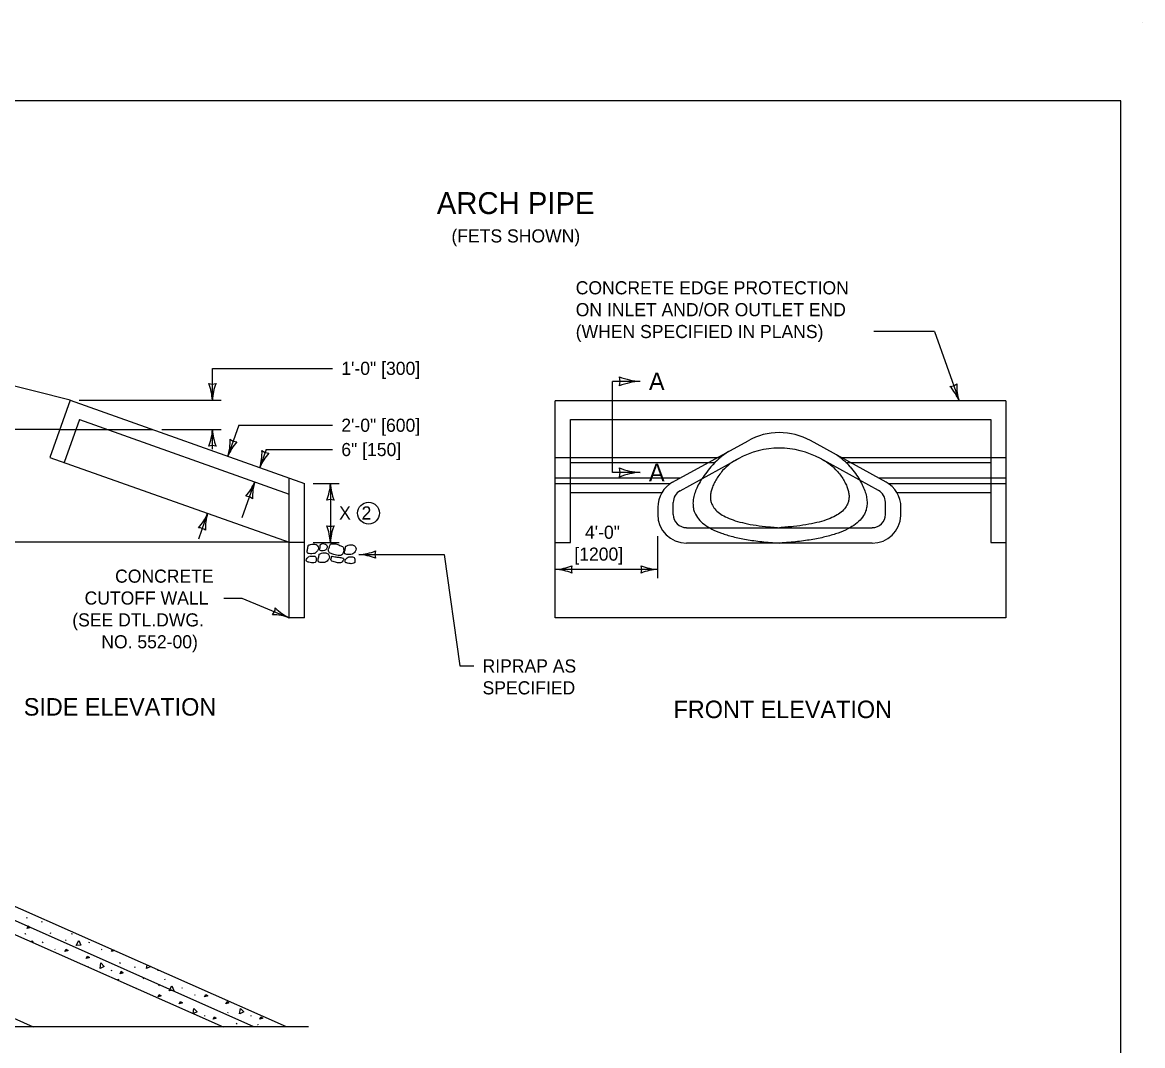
# Model space of a CAD drawing. Extents: x 49991.4 to 50021, y 49987.6 to 50011.4.
# Drawn here: x 50015.92 to 50021.04, y 50003.85 to 50008.52 of the extents above; entities that cross this region are included whole.
import ezdxf

# ---------------------------------------------------------------- set-up
doc = ezdxf.new("R2010")
doc.units = 0
for name, color, linetype in [('Level 1', 7, 'Continuous'), ('Level 2', 7, 'Continuous'), ('Level 3', 7, 'Continuous'), ('Level 4', 7, 'Continuous'), ('Level 6', 7, 'Continuous')]:
    doc.layers.add(name, color=color, linetype=linetype)

msp = doc.modelspace()

# ---------------------------------------------------------------- linework, layer by layer
at = {"layer": 'Level 1'}
for p, q in [((50021.0378, 50008.5236), (50021.0378, 50008.5236)), ((50016.1364, 50006.7969), (50015.5405, 50006.9461)), ((50016.1364, 50006.7969), (50016.0435, 50006.5354)), ((50016.1364, 50006.7969), (50017.2067, 50006.4165)), ((50020.413, 50006.7939), (50018.3534, 50006.7939)), ((50018.3534, 50005.8027), (50018.3534, 50006.7939)), ((50020.413, 50006.7939), (50020.413, 50005.8027)), ((50016.0887, 50006.6627), (50015.6302, 50006.6627)), ((50018.8896, 50006.4219), (50019.2342, 50006.6118)), ((50019.865, 50006.4228), (50019.5201, 50006.612)), ((50016.0435, 50006.5354), (50017.1373, 50006.1472)), ((50018.9237, 50006.3831), (50019.1893, 50006.5293)), ((50019.8309, 50006.3837), (50019.5648, 50006.5297)), ((50017.1373, 50005.8027), (50017.1373, 50006.4412)), ((50018.3534, 50006.4412), (50018.9246, 50006.4412)), ((50019.8314, 50006.4412), (50020.413, 50006.4412)), ((50017.2067, 50005.8027), (50017.2067, 50006.4165)), ((50018.3534, 50006.4165), (50018.8806, 50006.4165)), ((50019.8753, 50006.4165), (50020.413, 50006.4165)), ((50018.8924, 50006.2748), (50018.8924, 50006.3299)), ((50019.8624, 50006.2748), (50019.8624, 50006.3306)), ((50018.8215, 50006.3067), (50018.8215, 50006.2748)), ((50019.9331, 50006.2693), (50019.9332, 50006.3075)), ((50018.953, 50006.2141), (50019.8017, 50006.2141)), ((50017.1373, 50006.1472), (50015.6335, 50006.1472)), ((50017.3942, 50006.1287), (50017.3955, 50006.1295)), ((50019.8017, 50006.1433), (50018.953, 50006.1433)), ((50017.273, 50006.0923), (50017.2743, 50006.0931)), ((50017.2067, 50005.8027), (50017.1373, 50005.8027)), ((50020.413, 50005.8027), (50018.3534, 50005.8027)), ((50017.1247, 50003.9332), (50014.8623, 50004.9337)), ((50016.9755, 50003.9332), (50014.8922, 50004.8567)), ((50014.922, 50004.7792), (50016.8348, 50003.9332)), ((50015.938, 50004.4293), (50015.9398, 50004.4333)), ((50016.0055, 50004.4111), (50016.0073, 50004.4151)), ((50015.9287, 50004.3596), (50015.9304, 50004.3569)), ((50015.9304, 50004.3586), (50015.9322, 50004.3559)), ((50016.0459, 50004.3596), (50016.0477, 50004.3636)), ((50016.1413, 50004.3596), (50016.1431, 50004.3569)), ((50016.1431, 50004.3586), (50016.1449, 50004.3559)), ((50016.0099, 50004.3165), (50016.0117, 50004.3205)), ((50016.0654, 50004.2881), (50016.0672, 50004.2854)), ((50016.1151, 50004.3267), (50016.1169, 50004.3307)), ((50016.2226, 50004.3165), (50016.2244, 50004.3205)), ((50016.2781, 50004.2881), (50016.2799, 50004.2854)), ((50016.219, 50004.2056), (50016.2199, 50004.2077)), ((50016.3237, 50004.1926), (50016.3242, 50004.1886)), ((50016.3634, 50004.2219), (50016.3651, 50004.2259)), ((50016.4309, 50004.2037), (50016.4326, 50004.2077)), ((50016.5364, 50004.1926), (50016.5369, 50004.1886)), ((50016.354, 50004.1522), (50016.3558, 50004.1495)), ((50016.3558, 50004.1512), (50016.3576, 50004.1485)), ((50016.4713, 50004.1522), (50016.473, 50004.1562)), ((50016.5667, 50004.1522), (50016.5685, 50004.1495)), ((50016.5685, 50004.1512), (50016.5703, 50004.1485)), ((50016.4356, 50004.1098), (50016.4371, 50004.1131)), ((50016.5405, 50004.1193), (50016.5423, 50004.1233)), ((50016.648, 50004.1091), (50016.6498, 50004.1131)), ((50016.7035, 50004.0807), (50016.7053, 50004.078)), ((50016.7491, 50003.9851), (50016.7495, 50003.9811)), ((50016.7887, 50004.0145), (50016.7905, 50004.0185)), ((50016.8562, 50003.9963), (50016.858, 50004.0003)), ((50016.9618, 50003.9851), (50016.9622, 50003.9811)), ((50016.8966, 50003.9448), (50016.8984, 50003.9488)), ((50016.9921, 50003.9448), (50016.9939, 50003.9421)), ((50016.9939, 50003.9438), (50016.9957, 50003.9411)), ((50017.1247, 50003.9332), (50017.1247, 50003.9332))]:
    msp.add_line(p, q, dxfattribs=at)
msp.add_lwpolyline([(50020.9378, 50008.1646), (50009.7374, 50008.1646), (50009.7374, 49999.8856), (50020.9378, 49999.8856)], close=True, dxfattribs=at)
for points in [[(50015.9389, 50004.3827), (50015.9442, 50004.3938), (50015.9531, 50004.3871), (50015.9389, 50004.3827)], [(50015.9586, 50004.3207), (50015.962, 50004.3271), (50015.9664, 50004.3173)], [(50016.112, 50004.2765), (50016.1174, 50004.2876), (50016.1262, 50004.281), (50016.112, 50004.2765)], [(50016.1627, 50004.3045), (50016.1747, 50004.3271), (50016.184, 50004.3063), (50016.1631, 50004.3045)], [(50016.3247, 50004.2765), (50016.3289, 50004.2851)], [(50016.2094, 50004.2448), (50016.2147, 50004.2559), (50016.2236, 50004.2492), (50016.2094, 50004.2448)], [(50016.3385, 50004.2809), (50016.3247, 50004.2765)], [(50016.2722, 50004.1991), (50016.2757, 50004.2245), (50016.2916, 50004.2081), (50016.2726, 50004.1993)], [(50016.3643, 50004.1753), (50016.3696, 50004.1864), (50016.3785, 50004.1797), (50016.3643, 50004.1753)], [(50016.4849, 50004.1991), (50016.4871, 50004.2152)], [(50016.5037, 50004.2078), (50016.4853, 50004.1993)], [(50016.5769, 50004.1753), (50016.577, 50004.1754)], [(50016.5771, 50004.1754), (50016.5769, 50004.1753)], [(50016.5374, 50004.0691), (50016.5427, 50004.0802), (50016.5516, 50004.0736), (50016.5374, 50004.0691)], [(50016.588, 50004.0971), (50016.6, 50004.1197), (50016.6094, 50004.0989), (50016.5885, 50004.0971)], [(50016.7501, 50004.0691), (50016.7554, 50004.0802), (50016.7643, 50004.0736), (50016.7501, 50004.0691)], [(50016.6347, 50004.0374), (50016.6401, 50004.0485), (50016.649, 50004.0418), (50016.6347, 50004.0374)], [(50016.8474, 50004.0374), (50016.8528, 50004.0485), (50016.8616, 50004.0418), (50016.8474, 50004.0374)], [(50016.6979, 50003.9938), (50016.7011, 50004.0171), (50016.717, 50004.0007), (50016.7, 50003.9928)], [(50016.7896, 50003.9679), (50016.795, 50003.979), (50016.8038, 50003.9723), (50016.7896, 50003.9679)], [(50016.9102, 50003.9917), (50016.9138, 50004.0171), (50016.9297, 50004.0007), (50016.9107, 50003.9919)], [(50017.0023, 50003.9679), (50017.0076, 50003.979), (50017.0165, 50003.9723), (50017.0023, 50003.9679)]]:
    msp.add_lwpolyline(points, dxfattribs=at)
for centre, major_axis, start_param, end_param in [((50019.3773, 50006.3519), (0, 0.2967), 5.781332, 6.786673), ((50019.3773, 50006.188), (0, 0.3897), 5.781311, 6.786734), ((50019.3162, 50006.2891), (0, 0.2717), 0.485979, 0.816691), ((50019.4459, 50006.2851), (0, 0.2717), 5.466495, 5.799741), ((50018.953, 50006.3067), (0, 0.1315), 0.503156, 1.570796), ((50018.953, 50006.3299), (0, 0.0606), 0.503453, 1.570796), ((50019.8017, 50006.3306), (0, 0.0606), 4.712389, 5.781265), ((50019.8017, 50006.3075), (0, 0.1315), 4.712389, 5.781202), ((50018.953, 50006.2748), (0, -0.1315), 4.712389, 6.283185), ((50018.953, 50006.2748), (0, -0.0606), 4.712389, 6.283185), ((50019.8017, 50006.2748), (0, -0.0606), 0, 1.570796), ((50019.8017, 50006.2748), (0, -0.1315), 0, 1.528873)]:
    msp.add_ellipse(centre, major_axis=major_axis, ratio=0.999965, start_param=start_param, end_param=end_param, dxfattribs=at)
for points in [[(50019.1181, 50006.4752), (50018.9295, 50006.242), (50019.3774, 50006.2141)], [(50019.6439, 50006.4711), (50019.825, 50006.2419), (50019.3774, 50006.2141)]]:
    msp.add_open_spline(points, degree=2, dxfattribs=at)
for points in [[(50017.2229, 50006.1324), (50017.2349, 50006.1374), (50017.2476, 50006.139), (50017.2609, 50006.1367), (50017.267, 50006.1315), (50017.271, 50006.1205), (50017.2664, 50006.1088), (50017.2534, 50006.0968), (50017.2411, 50006.0953), (50017.2284, 50006.0956), (50017.2204, 50006.0986), (50017.2192, 50006.1083), (50017.2207, 50006.1162), (50017.2225, 50006.1247), (50017.2243, 50006.133)], [(50017.28, 50006.1364), (50017.2857, 50006.1409), (50017.2975, 50006.1401), (50017.3081, 50006.1356), (50017.3105, 50006.1236), (50017.3038, 50006.1121), (50017.2922, 50006.1088), (50017.2763, 50006.1114), (50017.2763, 50006.1191), (50017.2785, 50006.1268), (50017.2782, 50006.1346), (50017.2802, 50006.1369)], [(50017.3158, 50006.1124), (50017.3205, 50006.1263), (50017.3257, 50006.1384), (50017.3332, 50006.1402), (50017.3496, 50006.1397), (50017.3687, 50006.133), (50017.383, 50006.1249), (50017.386, 50006.1088), (50017.3781, 50006.0906), (50017.3666, 50006.0863), (50017.3411, 50006.092), (50017.3243, 50006.0976), (50017.3163, 50006.1069), (50017.3158, 50006.1126)], [(50017.3942, 50006.1287), (50017.4063, 50006.1337), (50017.4189, 50006.1355), (50017.4321, 50006.133), (50017.4384, 50006.1278), (50017.4424, 50006.1168), (50017.4377, 50006.1051), (50017.4247, 50006.0932), (50017.4125, 50006.0915), (50017.3997, 50006.092), (50017.3917, 50006.0948), (50017.3904, 50006.1045), (50017.3921, 50006.1125), (50017.3938, 50006.1211), (50017.3955, 50006.1295)], [(50017.2293, 50006.0832), (50017.2367, 50006.0841), (50017.2452, 50006.0839), (50017.2542, 50006.0833), (50017.2585, 50006.0791), (50017.2595, 50006.0676), (50017.2594, 50006.0584), (50017.2493, 50006.0536), (50017.2271, 50006.056), (50017.2156, 50006.0616), (50017.2164, 50006.0705), (50017.2217, 50006.0774), (50017.2289, 50006.0829)], [(50017.273, 50006.0923), (50017.2851, 50006.0973), (50017.2977, 50006.0991), (50017.3109, 50006.0966), (50017.3172, 50006.0914), (50017.3212, 50006.0804), (50017.3165, 50006.0687), (50017.3035, 50006.0568), (50017.2913, 50006.0551), (50017.2785, 50006.0556), (50017.2705, 50006.0584), (50017.2692, 50006.0681), (50017.2709, 50006.0761), (50017.2726, 50006.0847), (50017.2743, 50006.0931)], [(50017.3335, 50006.0843), (50017.3454, 50006.0811), (50017.3633, 50006.0786), (50017.3821, 50006.0753), (50017.3854, 50006.073), (50017.3821, 50006.0619), (50017.3756, 50006.0546), (50017.3576, 50006.0538), (50017.3381, 50006.0592), (50017.3285, 50006.0642), (50017.3286, 50006.0734), (50017.3318, 50006.0825), (50017.3329, 50006.0843)], [(50017.4063, 50006.0794), (50017.4134, 50006.0806), (50017.422, 50006.0802), (50017.4312, 50006.0796), (50017.4354, 50006.0753), (50017.4364, 50006.064), (50017.4362, 50006.0547), (50017.4261, 50006.0499), (50017.4039, 50006.0522), (50017.3925, 50006.0578), (50017.3934, 50006.0667), (50017.3984, 50006.0736), (50017.4057, 50006.0793)]]:
    msp.add_spline(points, degree=3, dxfattribs=at)
at = {"layer": 'Level 2'}
msp.add_circle((50017.4997, 50006.2807), 0.05, dxfattribs=at)
at = {"layer": 'Level 3'}
for p, q in [((50020.0861, 50007.1106), (50019.8089, 50007.1106)), ((50020.0861, 50007.1106), (50020.1986, 50006.7939)), ((50016.7858, 50006.797), (50016.7858, 50006.9424)), ((50016.7858, 50006.9424), (50017.3351, 50006.9424)), ((50016.1764, 50006.797), (50016.8258, 50006.797)), ((50016.554, 50006.6627), (50016.8258, 50006.6627)), ((50016.7858, 50006.5732), (50016.7858, 50006.6627)), ((50016.907, 50006.6824), (50016.8567, 50006.5409)), ((50016.907, 50006.6824), (50017.3351, 50006.6824)), ((50017.032, 50006.5713), (50017.0027, 50006.489)), ((50017.032, 50006.5713), (50017.3351, 50006.5713)), ((50016.9214, 50006.2603), (50016.9795, 50006.4237)), ((50017.2467, 50006.416), (50017.3651, 50006.416)), ((50017.3251, 50006.416), (50017.3251, 50006.1469)), ((50016.7638, 50006.2797), (50016.7221, 50006.1623)), ((50017.2467, 50006.1469), (50017.3651, 50006.1469)), ((50018.8215, 50005.9833), (50018.8215, 50006.1748)), ((50017.4553, 50006.0911), (50017.8452, 50006.0911)), ((50017.8452, 50006.0911), (50017.9169, 50005.5821)), ((50018.8215, 50006.0233), (50018.3534, 50006.0233)), ((50016.8383, 50005.8926), (50016.9202, 50005.8926)), ((50016.9202, 50005.8926), (50017.1373, 50005.8027)), ((50017.9169, 50005.5821), (50017.9807, 50005.5821))]:
    msp.add_line(p, q, dxfattribs=at)
for centre, radius, start, end in [((50018.7528, 50007.1607), 0.2779, 247.456, 267.6395), ((50018.5811, 50006.883), 0.0685, 342.1388, 17.8612), ((50016.7858, 50006.9252), 0.0548, 252.1388, 287.8612), ((50016.5531, 50006.7855), 0.233, 2.8273, 22.0772), ((50017.0079, 50006.7878), 0.2223, 157.456, 177.6395), ((50018.7558, 50006.5921), 0.2912, 92.8273, 112.0772), ((50020.1557, 50006.9147), 0.0548, 271.6993, 307.4216), ((50019.9832, 50006.7052), 0.233, 22.3878, 41.6376), ((50020.411, 50006.8596), 0.2223, 177.0165, 197.2), ((50016.5637, 50006.6719), 0.2223, 337.456, 357.6395), ((50017.0185, 50006.6742), 0.233, 182.8273, 202.0772), ((50016.7858, 50006.5345), 0.0548, 72.1388, 107.8612), ((50016.6336, 50006.6081), 0.233, 343.2473, 2.4971), ((50017.0629, 50006.4578), 0.2223, 137.876, 158.0595), ((50016.8996, 50006.6617), 0.0548, 232.5588, 268.2812), ((50016.7796, 50006.5562), 0.233, 343.2474, 2.4973), ((50017.2089, 50006.4059), 0.2223, 137.8761, 158.0596), ((50017.0457, 50006.6098), 0.0548, 232.5589, 268.2813), ((50018.7528, 50006.7442), 0.2779, 247.456, 267.6395), ((50018.5811, 50006.4665), 0.0685, 342.1388, 17.8612), ((50018.7558, 50006.1756), 0.2912, 92.8273, 112.0772), ((50016.7732, 50006.5067), 0.2223, 317.8941, 338.0776), ((50017.2026, 50006.3566), 0.233, 163.2654, 182.5152), ((50017.103, 50006.4252), 0.2223, 337.456, 357.6395), ((50017.5578, 50006.4275), 0.233, 182.8273, 202.0772), ((50016.9365, 50006.3029), 0.0548, 52.5769, 88.2992), ((50017.3251, 50006.2878), 0.0548, 72.1388, 107.8612), ((50016.5576, 50006.3627), 0.2223, 317.8961, 338.0796), ((50016.987, 50006.2127), 0.233, 163.2674, 182.5172), ((50016.7209, 50006.1589), 0.0548, 52.5789, 88.3013), ((50017.3251, 50006.2751), 0.0548, 252.1388, 287.8612), ((50017.0924, 50006.1354), 0.233, 2.8273, 22.0772), ((50017.5472, 50006.1377), 0.2223, 157.456, 177.6395), ((50017.4438, 50006.3238), 0.233, 272.8273, 292.0772), ((50017.4461, 50005.869), 0.2223, 67.456, 87.6395), ((50017.5835, 50006.0911), 0.0548, 162.1388, 197.8612), ((50018.3419, 50006.256), 0.233, 272.8273, 292.0772), ((50018.3442, 50005.8012), 0.2223, 67.456, 87.6395), ((50018.4816, 50006.0233), 0.0548, 162.1388, 197.8612), ((50018.8307, 50006.2454), 0.2223, 247.456, 267.6395), ((50018.6933, 50006.0233), 0.0548, 342.1388, 17.8612), ((50018.833, 50005.7906), 0.233, 92.8273, 112.0772), ((50017.0188, 50005.8517), 0.0548, 319.6469, 355.3693), ((50017.2369, 50006.0133), 0.233, 225.431, 244.6808), ((50017.0608, 50005.594), 0.2223, 69.8686, 90.0521)]:
    msp.add_arc(centre, radius, start, end, dxfattribs=at)
at = {"layer": 'Level 4'}
for p, q in [((50016.1786, 50006.7083), (50016.109, 50006.5122)), ((50016.1786, 50006.7083), (50017.1373, 50006.3676)), ((50018.4227, 50006.7083), (50020.3436, 50006.7083)), ((50018.4227, 50006.1463), (50018.4227, 50006.7083)), ((50020.3436, 50006.7083), (50020.3436, 50006.1463)), ((50016.0887, 50006.6627), (50016.514, 50006.6627)), ((50018.3534, 50006.5354), (50019.1087, 50006.5354)), ((50019.654, 50006.5354), (50020.413, 50006.5354)), ((50018.4227, 50006.5122), (50019.0832, 50006.5122)), ((50019.6815, 50006.5122), (50020.3436, 50006.5122)), ((50018.4227, 50006.3749), (50018.8406, 50006.3749)), ((50019.9146, 50006.3749), (50020.3436, 50006.3749)), ((50017.1373, 50006.1472), (50017.2067, 50006.1472)), ((50018.3534, 50006.1463), (50018.4227, 50006.1463)), ((50020.3436, 50006.1463), (50020.413, 50006.1463)), ((50014.6729, 50004.5053), (50015.9669, 50003.9332))]:
    msp.add_line(p, q, dxfattribs=at)
for centre, radius, start, end in [((50019.3774, 50006.2143), 0.4187, 123.6589, 138.4291), ((50019.3753, 50006.1776), 0.4536, 43.9896, 54.5961)]:
    msp.add_arc(centre, radius, start, end, dxfattribs=at)
for points in [[(50019.0642, 50006.4921), (50018.8031, 50006.1815), (50019.3769, 50006.1433)], [(50019.7016, 50006.4926), (50019.9533, 50006.1815), (50019.3802, 50006.1433)]]:
    msp.add_open_spline(points, degree=2, dxfattribs=at)
at = {"layer": 'Level 6'}
for p, q in [((50018.6142, 50006.4665), (50018.6142, 50006.883)), ((50018.7414, 50006.883), (50018.6142, 50006.883)), ((50018.7366, 50006.4665), (50018.6142, 50006.4665)), ((50017.2247, 50003.9332), (50015.6344, 50003.9332))]:
    msp.add_line(p, q, dxfattribs=at)

# ---------------------------------------------------------------- texts
at = {"layer": 'Level 2'}
for s, height, p in [('ARCH PIPE', 0.1, (50017.8116, 50007.6477)), ('(FETS SHOWN)', 0.06, (50017.8786, 50007.5177)), ('CONCRETE EDGE PROTECTION', 0.06, (50018.4466, 50007.2806)), ('ON INLET AND/OR OUTLET END', 0.06, (50018.4466, 50007.1806)), ('(WHEN SPECIFIED IN PLANS)', 0.06, (50018.4466, 50007.0806)), ('1\'-0" [300]', 0.06, (50017.3751, 50006.9124)), ('A', 0.08, (50018.7814, 50006.843)), ('2\'-0" [600]', 0.06, (50017.3751, 50006.6524)), ('6" [150]', 0.06, (50017.3751, 50006.5413)), ('A', 0.08, (50018.7814, 50006.4265)), ('X', 0.06, (50017.3651, 50006.2514)), ('2', 0.06, (50017.4677, 50006.2514)), ('4\'-0"', 0.06, (50018.489, 50006.1633)), ('[1200]', 0.06, (50018.4403, 50006.0633)), ('CONCRETE', 0.06, (50016.3411, 50005.9626)), ('CUTOFF WALL', 0.06, (50016.2016, 50005.8626)), ('(SEE DTL.DWG.', 0.06, (50016.1453, 50005.7626)), ('NO. 552-00)', 0.06, (50016.278, 50005.6626)), ('RIPRAP AS', 0.06, (50018.0207, 50005.5521)), ('SPECIFIED', 0.06, (50018.0207, 50005.4521)), ('SIDE ELEVATION', 0.08, (50015.9235, 50005.3551)), ('FRONT ELEVATION', 0.08, (50018.8937, 50005.3437))]:
    msp.add_text(s, height=height, dxfattribs=at).set_placement(p)

doc.saveas('drawing.dxf')
